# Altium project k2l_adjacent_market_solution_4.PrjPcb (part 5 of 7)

## Sheet dac38j84_03.SchDoc
size 431 x 279 mm; Date: Not shown in title block; ApprovedBy: Not shown in title block; CheckedBy: Not shown in title block; Author: Not shown in title block; CompanyName: Not shown in title block; Engineer: Not shown in title block; Organization: Not shown in title block; Address1: Not shown in title block; Address2: Not shown in title block; Address3: Not shown in title block; Address4: Not shown in title block; DocumentNumber: 29; Revision: Use project parameter SCH_Rev; SheetNumber: 29; SheetTotal: 38; PageSetup: Record=PageOptions¦CenterHorizontal=True¦CenterVertical=True¦PrintScale=1.00¦XCorrection=1.00¦YCorrection=1.00¦PrintKind=0¦BorderSize=5000000¦LeftOffset=0¦BottomOffset=0¦Orientation=2¦PaperLength=1000¦PaperWidth=1000¦Scale=100¦PaperSource=15¦PrintQuality=600¦MediaType=1¦DitherType=10¦PaperKind=Letter¦PrintScaleMode=1
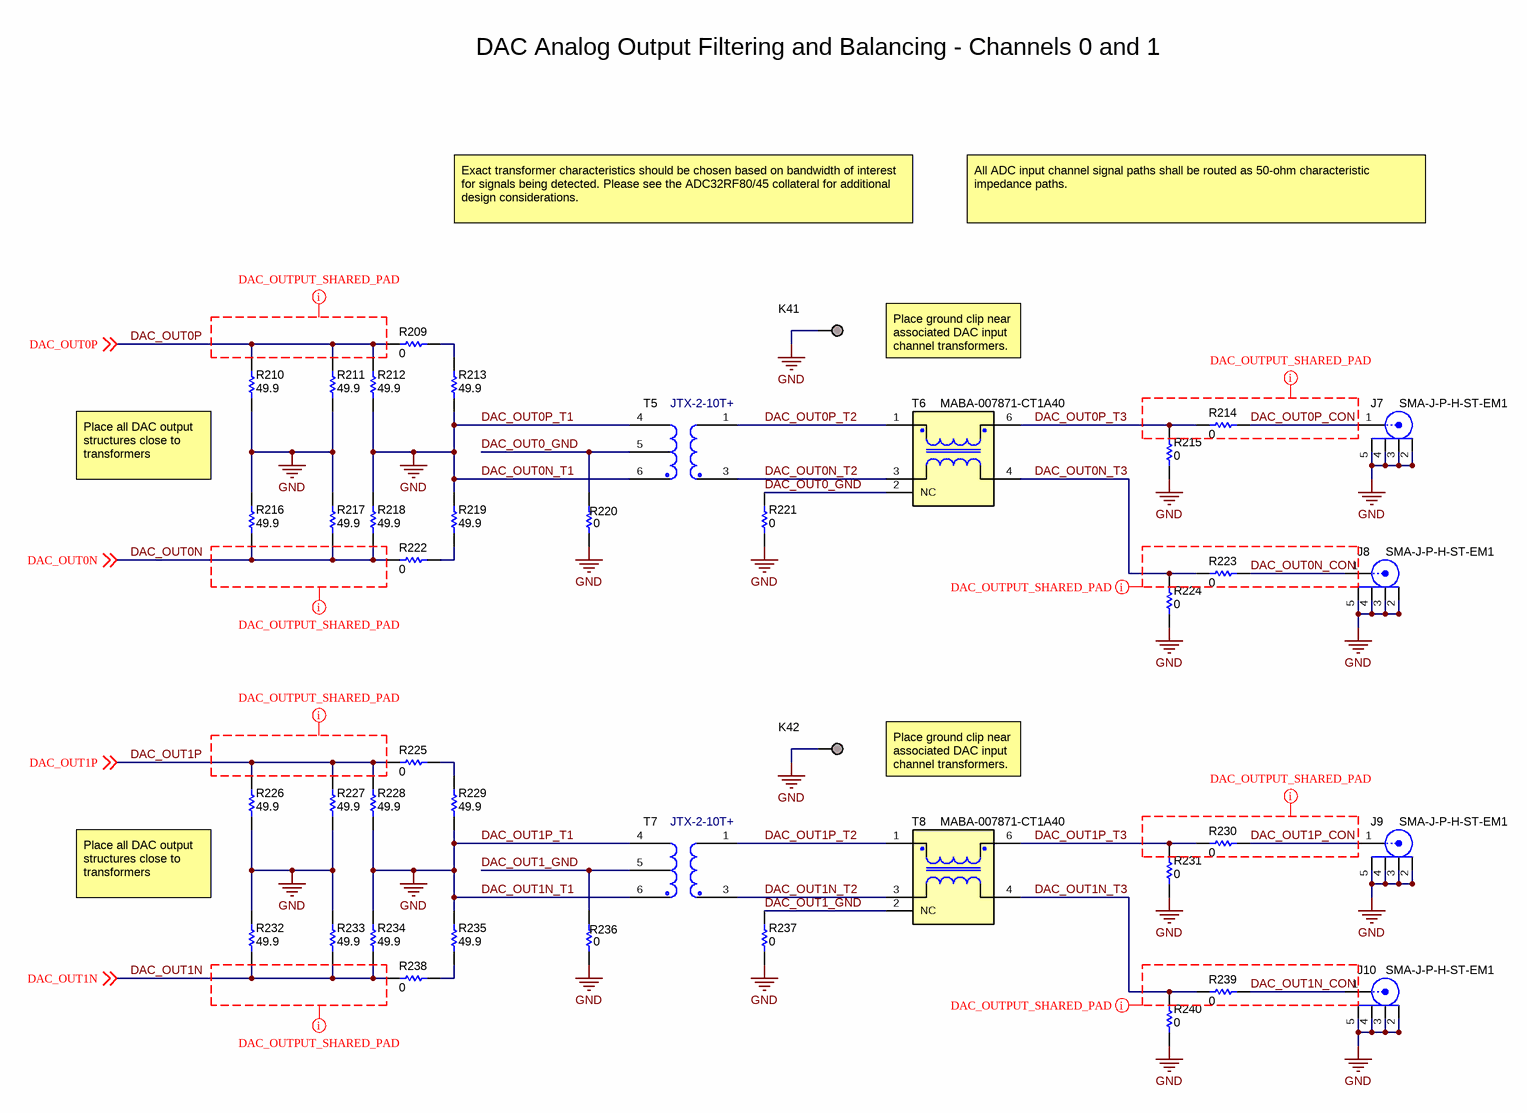
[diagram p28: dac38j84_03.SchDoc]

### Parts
J7  SMA-J-P-H-ST-EM1  [Samtec_SMA-J-P-H-ST-EM1]
J8  SMA-J-P-H-ST-EM1  [Samtec_SMA-J-P-H-ST-EM1]
J9  SMA-J-P-H-ST-EM1  [Samtec_SMA-J-P-H-ST-EM1]
J10  SMA-J-P-H-ST-EM1  [Samtec_SMA-J-P-H-ST-EM1]
K41  TESTPOINT  [TESTPOINT]  (value not drawn)  (no BOM)
K42  TESTPOINT  [TESTPOINT]  (value not drawn)  (no BOM)
R209  ValueDisplayed: 0  [0402]  (hidden comment: CRCW04020000Z0ED)
R210  ValueDisplayed: 49.9  [0402]  (hidden comment: CRCW040249R9FKED)
R211  ValueDisplayed: 49.9  [0402]  (hidden comment: CRCW040249R9FKED)
R212  ValueDisplayed: 49.9  [0402]  (hidden comment: CRCW040249R9FKED)
R213  ValueDisplayed: 49.9  [0402]  (hidden comment: CRCW040249R9FKED)
R214  ValueDisplayed: 0  [0402]  (hidden comment: CRCW04020000Z0ED)
R215  ValueDisplayed: 0  [0402]  (hidden comment: CRCW04020000Z0ED)
R216  ValueDisplayed: 49.9  [0402]  (hidden comment: CRCW040249R9FKED)
R217  ValueDisplayed: 49.9  [0402]  (hidden comment: CRCW040249R9FKED)
R218  ValueDisplayed: 49.9  [0402]  (hidden comment: CRCW040249R9FKED)
R219  ValueDisplayed: 49.9  [0402]  (hidden comment: CRCW040249R9FKED)
R220  ValueDisplayed: 0  [0402]  (hidden comment: CRCW04020000Z0ED)
R221  ValueDisplayed: 0  [0402]  (hidden comment: CRCW04020000Z0ED)
R222  ValueDisplayed: 0  [0402]  (hidden comment: CRCW04020000Z0ED)
R223  ValueDisplayed: 0  [0402]  (hidden comment: CRCW04020000Z0ED)
R224  ValueDisplayed: 0  [0402]  (hidden comment: CRCW04020000Z0ED)
R225  ValueDisplayed: 0  [0402]  (hidden comment: CRCW04020000Z0ED)
R226  ValueDisplayed: 49.9  [0402]  (hidden comment: CRCW040249R9FKED)
R227  ValueDisplayed: 49.9  [0402]  (hidden comment: CRCW040249R9FKED)
R228  ValueDisplayed: 49.9  [0402]  (hidden comment: CRCW040249R9FKED)
R229  ValueDisplayed: 49.9  [0402]  (hidden comment: CRCW040249R9FKED)
R230  ValueDisplayed: 0  [0402]  (hidden comment: CRCW04020000Z0ED)
R231  ValueDisplayed: 0  [0402]  (hidden comment: CRCW04020000Z0ED)
R232  ValueDisplayed: 49.9  [0402]  (hidden comment: CRCW040249R9FKED)
R233  ValueDisplayed: 49.9  [0402]  (hidden comment: CRCW040249R9FKED)
R234  ValueDisplayed: 49.9  [0402]  (hidden comment: CRCW040249R9FKED)
R235  ValueDisplayed: 49.9  [0402]  (hidden comment: CRCW040249R9FKED)
R236  ValueDisplayed: 0  [0402]  (hidden comment: CRCW04020000Z0ED)
R237  ValueDisplayed: 0  [0402]  (hidden comment: CRCW04020000Z0ED)
R238  ValueDisplayed: 0  [0402]  (hidden comment: CRCW04020000Z0ED)
R239  ValueDisplayed: 0  [0402]  (hidden comment: CRCW04020000Z0ED)
R240  ValueDisplayed: 0  [0402]  (hidden comment: CRCW04020000Z0ED)
T5  JTX-2-10T+  [Mini-Circuits_BH292]
T6  MABA-007871-CT1A40  [MACOM_MABA-007871]
T7  JTX-2-10T+  [Mini-Circuits_BH292]
T8  MABA-007871-CT1A40  [MACOM_MABA-007871]

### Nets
DAC_OUT0N_T1: J7.2 J7.3 J7.4 J7.5 J8.2 J8.3 J8.4 J8.5 J9.2 J9.3 J9.4 J9.5 J10.2 J10.3 J10.4 J10.5 K41.1 K42.1 R210.1 R211.1 R212.1 R213.1 R215.1 R216.2 R217.2 R218.2 R219.2 R220.1 R221.1 R224.1 R226.1 R227.1 R228.1 R229.1 R231.1 R232.2 R233.2 R234.2 R235.2 R236.1 R237.1 R240.1 T5.4 T5.6 T7.4 T7.6  [also labelled DAC_OUT0P_T1, DAC_OUT1N_T1, DAC_OUT1P_T1, GND]
DAC_OUT0_GND: R220.2 R221.2 T5.5 T6.2(NC)
DAC_OUT0N: R216.1 R217.1 R218.1 R222.2 ; off-sheet DAC_OUT0N
DAC_OUT0N_CON: J8.1 R223.2
DAC_OUT0N_T2: T5.3 T6.3
DAC_OUT0N_T3: R223.1 R224.2 T6.4(GND)
DAC_OUT0P: R209.2 R210.2 R211.2 R212.2 ; off-sheet DAC_OUT0P
DAC_OUT0P_CON: J7.1 R214.2
DAC_OUT0P_T2: T5.1 T6.1
DAC_OUT0P_T3: R214.1 R215.2 T6.6
DAC_OUT1_GND: R236.2 R237.2 T7.5 T8.2(NC)
DAC_OUT1N: R232.1 R233.1 R234.1 R238.2 ; off-sheet DAC_OUT1N
DAC_OUT1N_CON: J10.1 R239.2
DAC_OUT1N_T2: T7.3 T8.3
DAC_OUT1N_T3: R239.1 R240.2 T8.4(GND)
DAC_OUT1P: R225.2 R226.2 R227.2 R228.2 ; off-sheet DAC_OUT1P
DAC_OUT1P_CON: J9.1 R230.2
DAC_OUT1P_T2: T7.1 T8.1
DAC_OUT1P_T3: R230.1 R231.2 T8.6
NetR209_1: R209.1 R213.2
NetR219_1: R219.1 R222.1
NetR225_1: R225.1 R229.2
NetR235_1: R235.1 R238.1

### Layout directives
net class Undefined: (no net found under the mark), DAC_OUT0N_CON, DAC_OUT0P_CON, DAC_OUT1N_CON, DAC_OUT1P_CON

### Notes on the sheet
- DAC Analog Output Filtering and Balancing - Channels 0 and 1
- Exact transformer characteristics should be chosen based on bandwidth of interest for signals being detected. Please see the ADC32RF80/45 collateral for additional design considerations.
- All ADC input channel signal paths shall be routed as 50-ohm characteristic impedance paths.
- Place ground clip near associated DAC input channel transformers.
- Place all DAC output
  structures close to transformers

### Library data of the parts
J7-J10 = SMA-J-P-H-ST-EM1: SMA Jack, 50 Ohm, Gold, R/A, SMT; Manufacturer: Samtec; SymbolCreator: X0208326; Pitch_mm: 2.825; Gender: Female; Shrouded: Y; Voltage_V: 335
K41 K42 = TESTPOINT: TEST POINT.  No entry in BOM.
R209 R214 R215 R220-R225 R230 R231 R236-R240 = CRCW04020000Z0ED: RES, 0, 5%, 0.063 W, 0402; Manufacturer: Vishay-Dale; CompType: Resistor; Value: 0; Value_Code: 0000; Tolerance_%: 5; Power_W: 0.063; Value2: 0.063W; VDC_V: 50; TempCo: 200 ppm/C; SizeArea_mm2: 0.5; SizeX_mm: 1; SizeZ_mm: 0.6; EIA_Code: E24; U/M: EA; AEC Category: Q200
R210-R213 R216-R219 R226-R229 R232-R235 = CRCW040249R9FKED: RES, 49.9, 1%, 0.063 W, 0402; Manufacturer: Vishay-Dale; CompType: Resistor; Value: 49.9; Value_Code: 49R9; Tolerance_%: 1; Power_W: 0.063; Value2: 0.063W; VDC_V: 50; TempCo: 100 ppm/C; SizeArea_mm2: 0.5; SizeZ_mm: 0.6; EIA_Code: E96; U/M: EA; AEC Category: Q200
T5 T7 = JTX-2-10T+: RF Transformer, SMT; Manufacturer: Minicircuits; SymbolCreator: x0208325
T6 T8 = MABA-007871-CT1A40: Transformer, SMT; Manufacturer: MACOM; SymbolCreator: Altium; Ns1toNp: 1; SizeAreaWB_mm2: 27.1962; SizeArea_mm2: 17.7662; SizeX_mm: 4.21; SizeY_mm: 4.22; SizeZ_mm: 2.926

## Sheet dac38j84_04.SchDoc
size 431 x 279 mm; Date: Not shown in title block; ApprovedBy: Not shown in title block; CheckedBy: Not shown in title block; Author: Not shown in title block; CompanyName: Not shown in title block; Engineer: Not shown in title block; Organization: Not shown in title block; Address1: Not shown in title block; Address2: Not shown in title block; Address3: Not shown in title block; Address4: Not shown in title block; DocumentNumber: 30; Revision: Use project parameter SCH_Rev; SheetNumber: 30; SheetTotal: 38; PageSetup: Record=PageOptions¦CenterHorizontal=True¦CenterVertical=True¦PrintScale=1.00¦XCorrection=1.00¦YCorrection=1.00¦PrintKind=0¦BorderSize=5000000¦LeftOffset=0¦BottomOffset=0¦Orientation=2¦PaperLength=1000¦PaperWidth=1000¦Scale=100¦PaperSource=15¦PrintQuality=600¦MediaType=1¦DitherType=10¦PaperKind=Letter¦PrintScaleMode=1
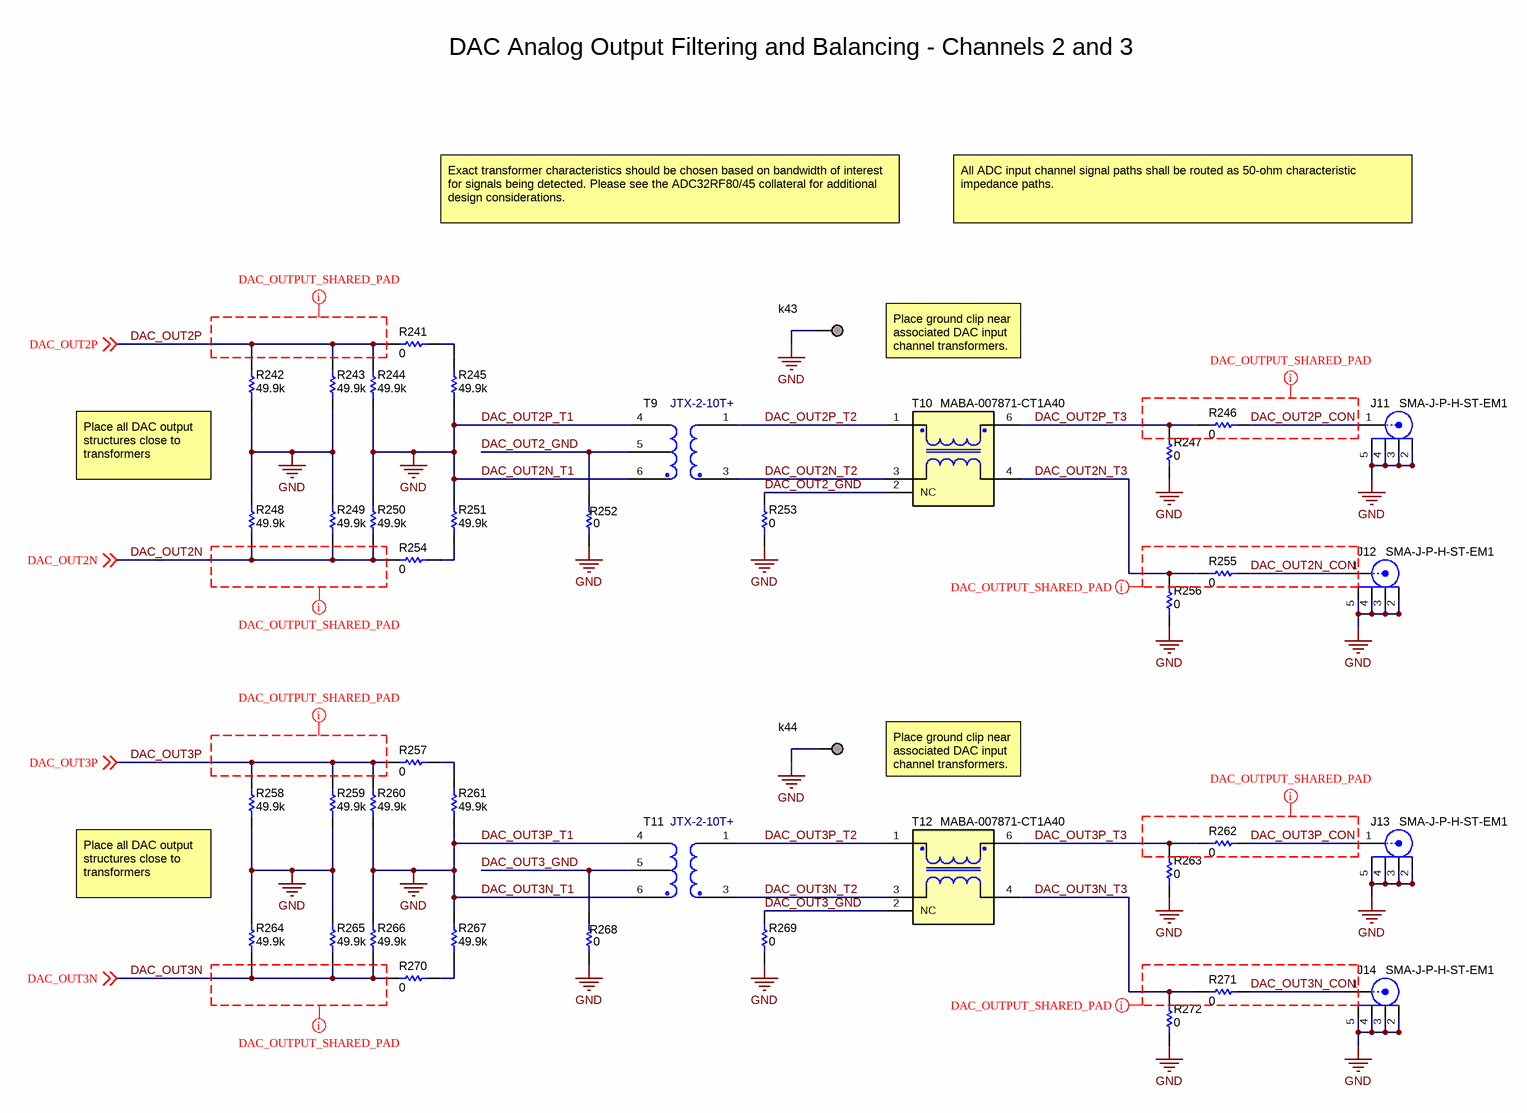
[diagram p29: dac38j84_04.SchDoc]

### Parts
J11  SMA-J-P-H-ST-EM1  [Samtec_SMA-J-P-H-ST-EM1]
J12  SMA-J-P-H-ST-EM1  [Samtec_SMA-J-P-H-ST-EM1]
J13  SMA-J-P-H-ST-EM1  [Samtec_SMA-J-P-H-ST-EM1]
J14  SMA-J-P-H-ST-EM1  [Samtec_SMA-J-P-H-ST-EM1]
k43  TESTPOINT  [TESTPOINT]  (value not drawn)  (no BOM)
k44  TESTPOINT  [TESTPOINT]  (value not drawn)  (no BOM)
R241  ValueDisplayed: 0  [0402]  (hidden comment: CRCW04020000Z0ED)
R242  ValueDisplayed: 49.9k  [0402]  (hidden comment: CRCW040249K9FKED)
R243  ValueDisplayed: 49.9k  [0402]  (hidden comment: CRCW040249K9FKED)
R244  ValueDisplayed: 49.9k  [0402]  (hidden comment: CRCW040249K9FKED)
R245  ValueDisplayed: 49.9k  [0402]  (hidden comment: CRCW040249K9FKED)
R246  ValueDisplayed: 0  [0402]  (hidden comment: CRCW04020000Z0ED)
R247  ValueDisplayed: 0  [0402]  (hidden comment: CRCW04020000Z0ED)
R248  ValueDisplayed: 49.9k  [0402]  (hidden comment: CRCW040249K9FKED)
R249  ValueDisplayed: 49.9k  [0402]  (hidden comment: CRCW040249K9FKED)
R250  ValueDisplayed: 49.9k  [0402]  (hidden comment: CRCW040249K9FKED)
R251  ValueDisplayed: 49.9k  [0402]  (hidden comment: CRCW040249K9FKED)
R252  ValueDisplayed: 0  [0402]  (hidden comment: CRCW04020000Z0ED)
R253  ValueDisplayed: 0  [0402]  (hidden comment: CRCW04020000Z0ED)
R254  ValueDisplayed: 0  [0402]  (hidden comment: CRCW04020000Z0ED)
R255  ValueDisplayed: 0  [0402]  (hidden comment: CRCW04020000Z0ED)
R256  ValueDisplayed: 0  [0402]  (hidden comment: CRCW04020000Z0ED)
R257  ValueDisplayed: 0  [0402]  (hidden comment: CRCW04020000Z0ED)
R258  ValueDisplayed: 49.9k  [0402]  (hidden comment: CRCW040249K9FKED)
R259  ValueDisplayed: 49.9k  [0402]  (hidden comment: CRCW040249K9FKED)
R260  ValueDisplayed: 49.9k  [0402]  (hidden comment: CRCW040249K9FKED)
R261  ValueDisplayed: 49.9k  [0402]  (hidden comment: CRCW040249K9FKED)
R262  ValueDisplayed: 0  [0402]  (hidden comment: CRCW04020000Z0ED)
R263  ValueDisplayed: 0  [0402]  (hidden comment: CRCW04020000Z0ED)
R264  ValueDisplayed: 49.9k  [0402]  (hidden comment: CRCW040249K9FKED)
R265  ValueDisplayed: 49.9k  [0402]  (hidden comment: CRCW040249K9FKED)
R266  ValueDisplayed: 49.9k  [0402]  (hidden comment: CRCW040249K9FKED)
R267  ValueDisplayed: 49.9k  [0402]  (hidden comment: CRCW040249K9FKED)
R268  ValueDisplayed: 0  [0402]  (hidden comment: CRCW04020000Z0ED)
R269  ValueDisplayed: 0  [0402]  (hidden comment: CRCW04020000Z0ED)
R270  ValueDisplayed: 0  [0402]  (hidden comment: CRCW04020000Z0ED)
R271  ValueDisplayed: 0  [0402]  (hidden comment: CRCW04020000Z0ED)
R272  ValueDisplayed: 0  [0402]  (hidden comment: CRCW04020000Z0ED)
T9  JTX-2-10T+  [Mini-Circuits_BH292]
T10  MABA-007871-CT1A40  [MACOM_MABA-007871]
T11  JTX-2-10T+  [Mini-Circuits_BH292]
T12  MABA-007871-CT1A40  [MACOM_MABA-007871]

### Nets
DAC_OUT2N_T1: J11.2 J11.3 J11.4 J11.5 J12.2 J12.3 J12.4 J12.5 J13.2 J13.3 J13.4 J13.5 J14.2 J14.3 J14.4 J14.5 k43.1 k44.1 R242.1 R243.1 R244.1 R245.1 R247.1 R248.2 R249.2 R250.2 R251.2 R252.1 R253.1 R256.1 R258.1 R259.1 R260.1 R261.1 R263.1 R264.2 R265.2 R266.2 R267.2 R268.1 R269.1 R272.1 T9.4 T9.6 T11.4 T11.6  [also labelled DAC_OUT2P_T1, DAC_OUT3N_T1, DAC_OUT3P_T1, GND]  [project net DAC_OUT0N_T1]
DAC_OUT2_GND: R252.2 R253.2 T9.5 T10.2(NC)
DAC_OUT2N: R248.1 R249.1 R250.1 R254.2 ; off-sheet DAC_OUT2N
DAC_OUT2N_CON: J12.1 R255.2
DAC_OUT2N_T2: T9.3 T10.3
DAC_OUT2N_T3: R255.1 R256.2 T10.4(GND)
DAC_OUT2P: R241.2 R242.2 R243.2 R244.2 ; off-sheet DAC_OUT2P
DAC_OUT2P_CON: J11.1 R246.2
DAC_OUT2P_T2: T9.1 T10.1
DAC_OUT2P_T3: R246.1 R247.2 T10.6
DAC_OUT3_GND: R268.2 R269.2 T11.5 T12.2(NC)
DAC_OUT3N: R264.1 R265.1 R266.1 R270.2 ; off-sheet DAC_OUT3N
DAC_OUT3N_CON: J14.1 R271.2
DAC_OUT3N_T2: T11.3 T12.3
DAC_OUT3N_T3: R271.1 R272.2 T12.4(GND)
DAC_OUT3P: R257.2 R258.2 R259.2 R260.2 ; off-sheet DAC_OUT3P
DAC_OUT3P_CON: J13.1 R262.2
DAC_OUT3P_T2: T11.1 T12.1
DAC_OUT3P_T3: R262.1 R263.2 T12.6
NetR241_1: R241.1 R245.2
NetR251_1: R251.1 R254.1
NetR257_1: R257.1 R261.2
NetR267_1: R267.1 R270.1

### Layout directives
net class Undefined: (no net found under the mark), DAC_OUT2N_CON, DAC_OUT2P_CON, DAC_OUT3N_CON, DAC_OUT3P_CON

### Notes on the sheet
- DAC Analog Output Filtering and Balancing - Channels 2 and 3
- Exact transformer characteristics should be chosen based on bandwidth of interest for signals being detected. Please see the ADC32RF80/45 collateral for additional design considerations.
- All ADC input channel signal paths shall be routed as 50-ohm characteristic impedance paths.
- Place ground clip near associated DAC input channel transformers.
- Place all DAC output
  structures close to transformers

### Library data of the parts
J11-J14 = SMA-J-P-H-ST-EM1: as J7-J10 on sheet dac38j84_03
k43 k44 = TESTPOINT: TEST POINT.  No entry in BOM.
R241 R246 R247 R252-R257 R262 R263 R268-R272 = CRCW04020000Z0ED: as R209 on sheet dac38j84_03
R242-R245 R248-R251 R258-R261 R264-R267 = CRCW040249K9FKED: RES, 49.9 k, 1%, 0.063 W, 0402; Manufacturer: Vishay-Dale; CompType: Resistor; Value: 49.9k; Res_ohm: 49900; Value_Code: 49k9; Tolerance_%: 1; Power_W: 0.063; Value2: 0.063W; VDC_V: 50; TempCo: 100 ppm/C; SizeArea_mm2: 0.5; SizeZ_mm: 0.6; EIA_Code: E96; U/M: EA; AEC Category: Q200
T9 T11 = JTX-2-10T+: as T5 on sheet dac38j84_03
T10 T12 = MABA-007871-CT1A40: as T6 on sheet dac38j84_03

## Sheet lmk04828_01.SchDoc
size 431 x 279 mm; Date: Not shown in title block; ApprovedBy: Not shown in title block; CheckedBy: Not shown in title block; Author: Not shown in title block; CompanyName: Not shown in title block; Engineer: Not shown in title block; Organization: Not shown in title block; Address1: Not shown in title block; Address2: Not shown in title block; Address3: Not shown in title block; Address4: Not shown in title block; DocumentNumber: 31; Revision: Use project parameter SCH_Rev; SheetNumber: 31; SheetTotal: 38; PageSetup: Record=PageOptions¦CenterHorizontal=True¦CenterVertical=True¦PrintScale=1.00¦XCorrection=1.00¦YCorrection=1.00¦PrintKind=0¦BorderSize=5000000¦LeftOffset=0¦BottomOffset=0¦Orientation=2¦PaperLength=1000¦PaperWidth=1000¦Scale=100¦PaperSource=15¦PrintQuality=600¦MediaType=1¦DitherType=10¦PaperKind=Letter¦PrintScaleMode=1
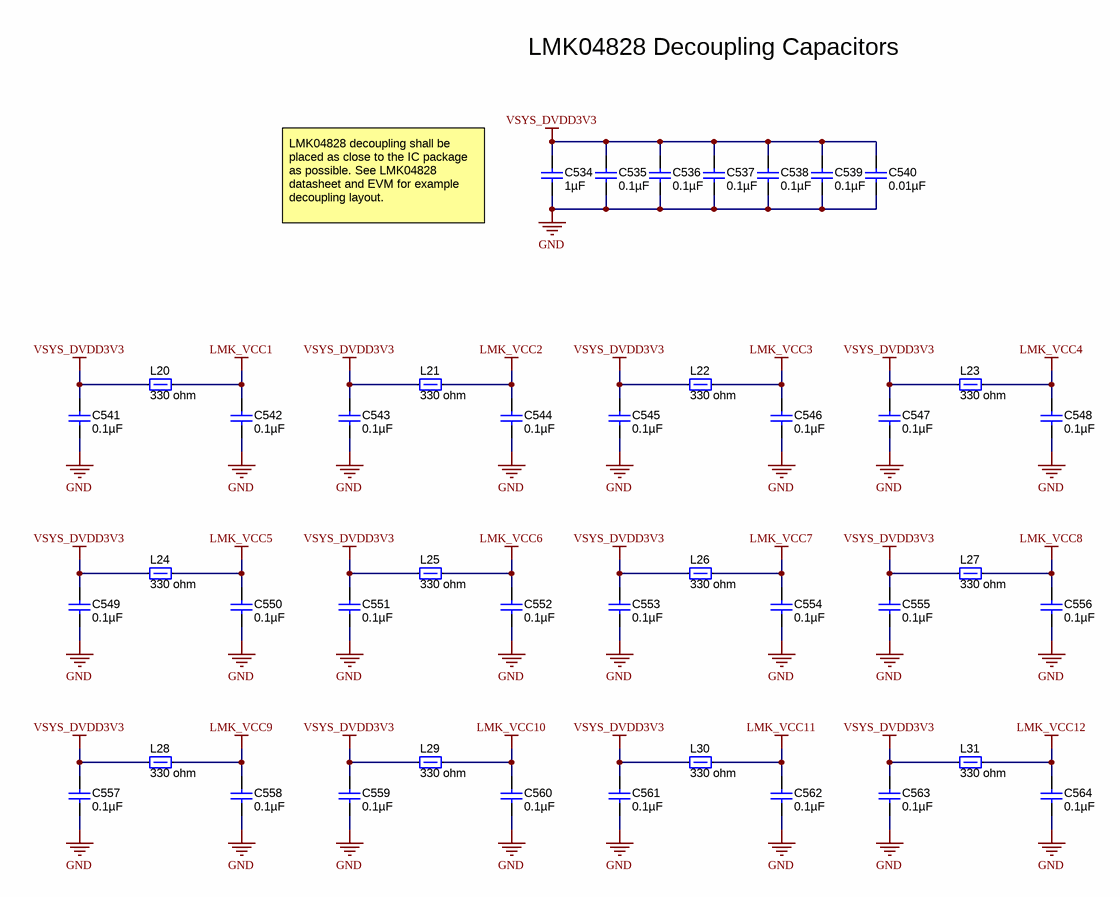
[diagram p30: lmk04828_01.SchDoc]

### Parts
C534  ValueDisplayed: 1µF  [0603L]  (hidden comment: C1608X5R1C105K)
C535  ValueDisplayed: 0.1µF  [0402L]  (hidden comment: C1005X5R1A104K)
C536  ValueDisplayed: 0.1µF  [0402L]  (hidden comment: C1005X5R1A104K)
C537  ValueDisplayed: 0.1µF  [0402L]  (hidden comment: C1005X5R1A104K)
C538  ValueDisplayed: 0.1µF  [0402L]  (hidden comment: C1005X5R1A104K)
C539  ValueDisplayed: 0.1µF  [0402L]  (hidden comment: C1005X5R1A104K)
C540  ValueDisplayed: 0.01µF  [0402L]  (hidden comment: C1005X7R1C103K)
C541  ValueDisplayed: 0.1µF  [0402L]  (hidden comment: C1005X5R1A104K)
C542  ValueDisplayed: 0.1µF  [0402L]  (hidden comment: C1005X5R1A104K)
C543  ValueDisplayed: 0.1µF  [0402L]  (hidden comment: C1005X5R1A104K)
C544  ValueDisplayed: 0.1µF  [0402L]  (hidden comment: C1005X5R1A104K)
C545  ValueDisplayed: 0.1µF  [0402L]  (hidden comment: C1005X5R1A104K)
C546  ValueDisplayed: 0.1µF  [0402L]  (hidden comment: C1005X5R1A104K)
C547  ValueDisplayed: 0.1µF  [0402L]  (hidden comment: C1005X5R1A104K)
C548  ValueDisplayed: 0.1µF  [0402L]  (hidden comment: C1005X5R1A104K)
C549  ValueDisplayed: 0.1µF  [0402L]  (hidden comment: C1005X5R1A104K)
C550  ValueDisplayed: 0.1µF  [0402L]  (hidden comment: C1005X5R1A104K)
C551  ValueDisplayed: 0.1µF  [0402L]  (hidden comment: C1005X5R1A104K)
C552  ValueDisplayed: 0.1µF  [0402L]  (hidden comment: C1005X5R1A104K)
C553  ValueDisplayed: 0.1µF  [0402L]  (hidden comment: C1005X5R1A104K)
C554  ValueDisplayed: 0.1µF  [0402L]  (hidden comment: C1005X5R1A104K)
C555  ValueDisplayed: 0.1µF  [0402L]  (hidden comment: C1005X5R1A104K)
C556  ValueDisplayed: 0.1µF  [0402L]  (hidden comment: C1005X5R1A104K)
C557  ValueDisplayed: 0.1µF  [0402L]  (hidden comment: C1005X5R1A104K)
C558  ValueDisplayed: 0.1µF  [0402L]  (hidden comment: C1005X5R1A104K)
C559  ValueDisplayed: 0.1µF  [0402L]  (hidden comment: C1005X5R1A104K)
C560  ValueDisplayed: 0.1µF  [0402L]  (hidden comment: C1005X5R1A104K)
C561  ValueDisplayed: 0.1µF  [0402L]  (hidden comment: C1005X5R1A104K)
C562  ValueDisplayed: 0.1µF  [0402L]  (hidden comment: C1005X5R1A104K)
C563  ValueDisplayed: 0.1µF  [0402L]  (hidden comment: C1005X5R1A104K)
C564  ValueDisplayed: 0.1µF  [0402L]  (hidden comment: C1005X5R1A104K)
L20  value 330 ohm  [0603]  (hidden comment: BLM18SG331TN1D)
L21  value 330 ohm  [0603]  (hidden comment: BLM18SG331TN1D)
L22  value 330 ohm  [0603]  (hidden comment: BLM18SG331TN1D)
L23  value 330 ohm  [0603]  (hidden comment: BLM18SG331TN1D)
L24  value 330 ohm  [0603]  (hidden comment: BLM18SG331TN1D)
L25  value 330 ohm  [0603]  (hidden comment: BLM18SG331TN1D)
L26  value 330 ohm  [0603]  (hidden comment: BLM18SG331TN1D)
L27  value 330 ohm  [0603]  (hidden comment: BLM18SG331TN1D)
L28  value 330 ohm  [0603]  (hidden comment: BLM18SG331TN1D)
L29  value 330 ohm  [0603]  (hidden comment: BLM18SG331TN1D)
L30  value 330 ohm  [0603]  (hidden comment: BLM18SG331TN1D)
L31  value 330 ohm  [0603]  (hidden comment: BLM18SG331TN1D)

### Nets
GND: C534.2 C535.2 C536.2 C537.2 C538.2 C539.2 C540.2 C541.2 C542.2 C543.2 C544.2 C545.2 C546.2 C547.2 C548.2 C549.2 C550.2 C551.2 C552.2 C553.2 C554.2 C555.2 C556.2 C557.2 C558.2 C559.2 C560.2 C561.2 C562.2 C563.2 C564.2  [project net DAC_OUT0N_T1]
LMK_VCC1: C542.1 L20.2
LMK_VCC2: C544.1 L21.2
LMK_VCC3: C546.1 L22.2
LMK_VCC4: C548.1 L23.2
LMK_VCC5: C550.1 L24.2
LMK_VCC6: C552.1 L25.2
LMK_VCC7: C554.1 L26.2
LMK_VCC8: C556.1 L27.2
LMK_VCC9: C558.1 L28.2
LMK_VCC10: C560.1 L29.2
LMK_VCC11: C562.1 L30.2
LMK_VCC12: C564.1 L31.2
VSYS_DVDD3V3: C534.1 C535.1 C536.1 C537.1 C538.1 C539.1 C540.1 C541.1 C543.1 C545.1 C547.1 C549.1 C551.1 C553.1 C555.1 C557.1 C559.1 C561.1 C563.1 L20.1 L21.1 L22.1 L23.1 L24.1 L25.1 L26.1 L27.1 L28.1 L29.1 L30.1 L31.1

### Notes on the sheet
- LMK04828 Decoupling Capacitors
- LMK04828 decoupling shall be placed as close to the IC package as possible. See LMK04828 datasheet and EVM for example decoupling layout.

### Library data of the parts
C534 = C1608X5R1C105K: CAP, CERM, 1uF, 16V, +/-10%, X5R, 0603; Manufacturer: TDK; Polarized: N; CompType: Capacitor; U/M: EA; Cap_F: 0.000001; Tolerance_%: 10; ESR_Ohm: 0.0057; Value1: 0.0057 ohm; VDC_V: 16; TaMin_C: -55; TaMax_C: 85; Cap_Case: 0603
C535-C539 C541-C564 = C1005X5R1A104K: CAP, CERM, 0.1uF, 10V, +/-10%, X5R, 0402; Manufacturer: TDK; Polarized: N; CompType: Capacitor; U/M: EA; Cap_F: 0.0000001; Tolerance_%: 10; ESR_Ohm: 0.0186; Value1: 0.0186 ohm; TaMin_C: -55; TaMax_C: 85; Cap_Case: 0402
C540 = C1005X7R1C103K: CAP, CERM, 0.01uF, 16V, +/-10%, X7R, 0402; Manufacturer: TDK; Polarized: N; CompType: Capacitor; U/M: EA; Cap_F: 0.00000001; Tolerance_%: 10; ESR_Ohm: 0.0623; Value1: 0.0623 ohm; VDC_V: 16; TaMin_C: -55; TaMax_C: 125; Cap_Case: 0402
L20-L31 = BLM18SG331TN1D: 1.5A Ferrite Bead, 330 ohm @ 100MHz, SMD; Manufacturer: MuRata; Imax_A: 1.5; DCR_ohm: 0.07; Value1: 0.07 ohm; ZTyp@100MHz_Ohm: 330; U/M: EA

## Sheet lmk04828_02.SchDoc
size 431 x 279 mm; Date: Not shown in title block; ApprovedBy: Not shown in title block; CheckedBy: Not shown in title block; Author: Not shown in title block; CompanyName: Not shown in title block; Engineer: Not shown in title block; Organization: Not shown in title block; Address1: Not shown in title block; Address2: Not shown in title block; Address3: Not shown in title block; Address4: Not shown in title block; DocumentNumber: 32; Revision: Use project parameter SCH_Rev; SheetNumber: 32; SheetTotal: 38; PageSetup: Record=PageOptions¦CenterHorizontal=True¦CenterVertical=True¦PrintScale=1.00¦XCorrection=1.00¦YCorrection=1.00¦PrintKind=0¦BorderSize=5000000¦LeftOffset=0¦BottomOffset=0¦Orientation=2¦PaperLength=1000¦PaperWidth=1000¦Scale=100¦PaperSource=15¦PrintQuality=600¦MediaType=1¦DitherType=10¦PaperKind=Letter¦PrintScaleMode=1
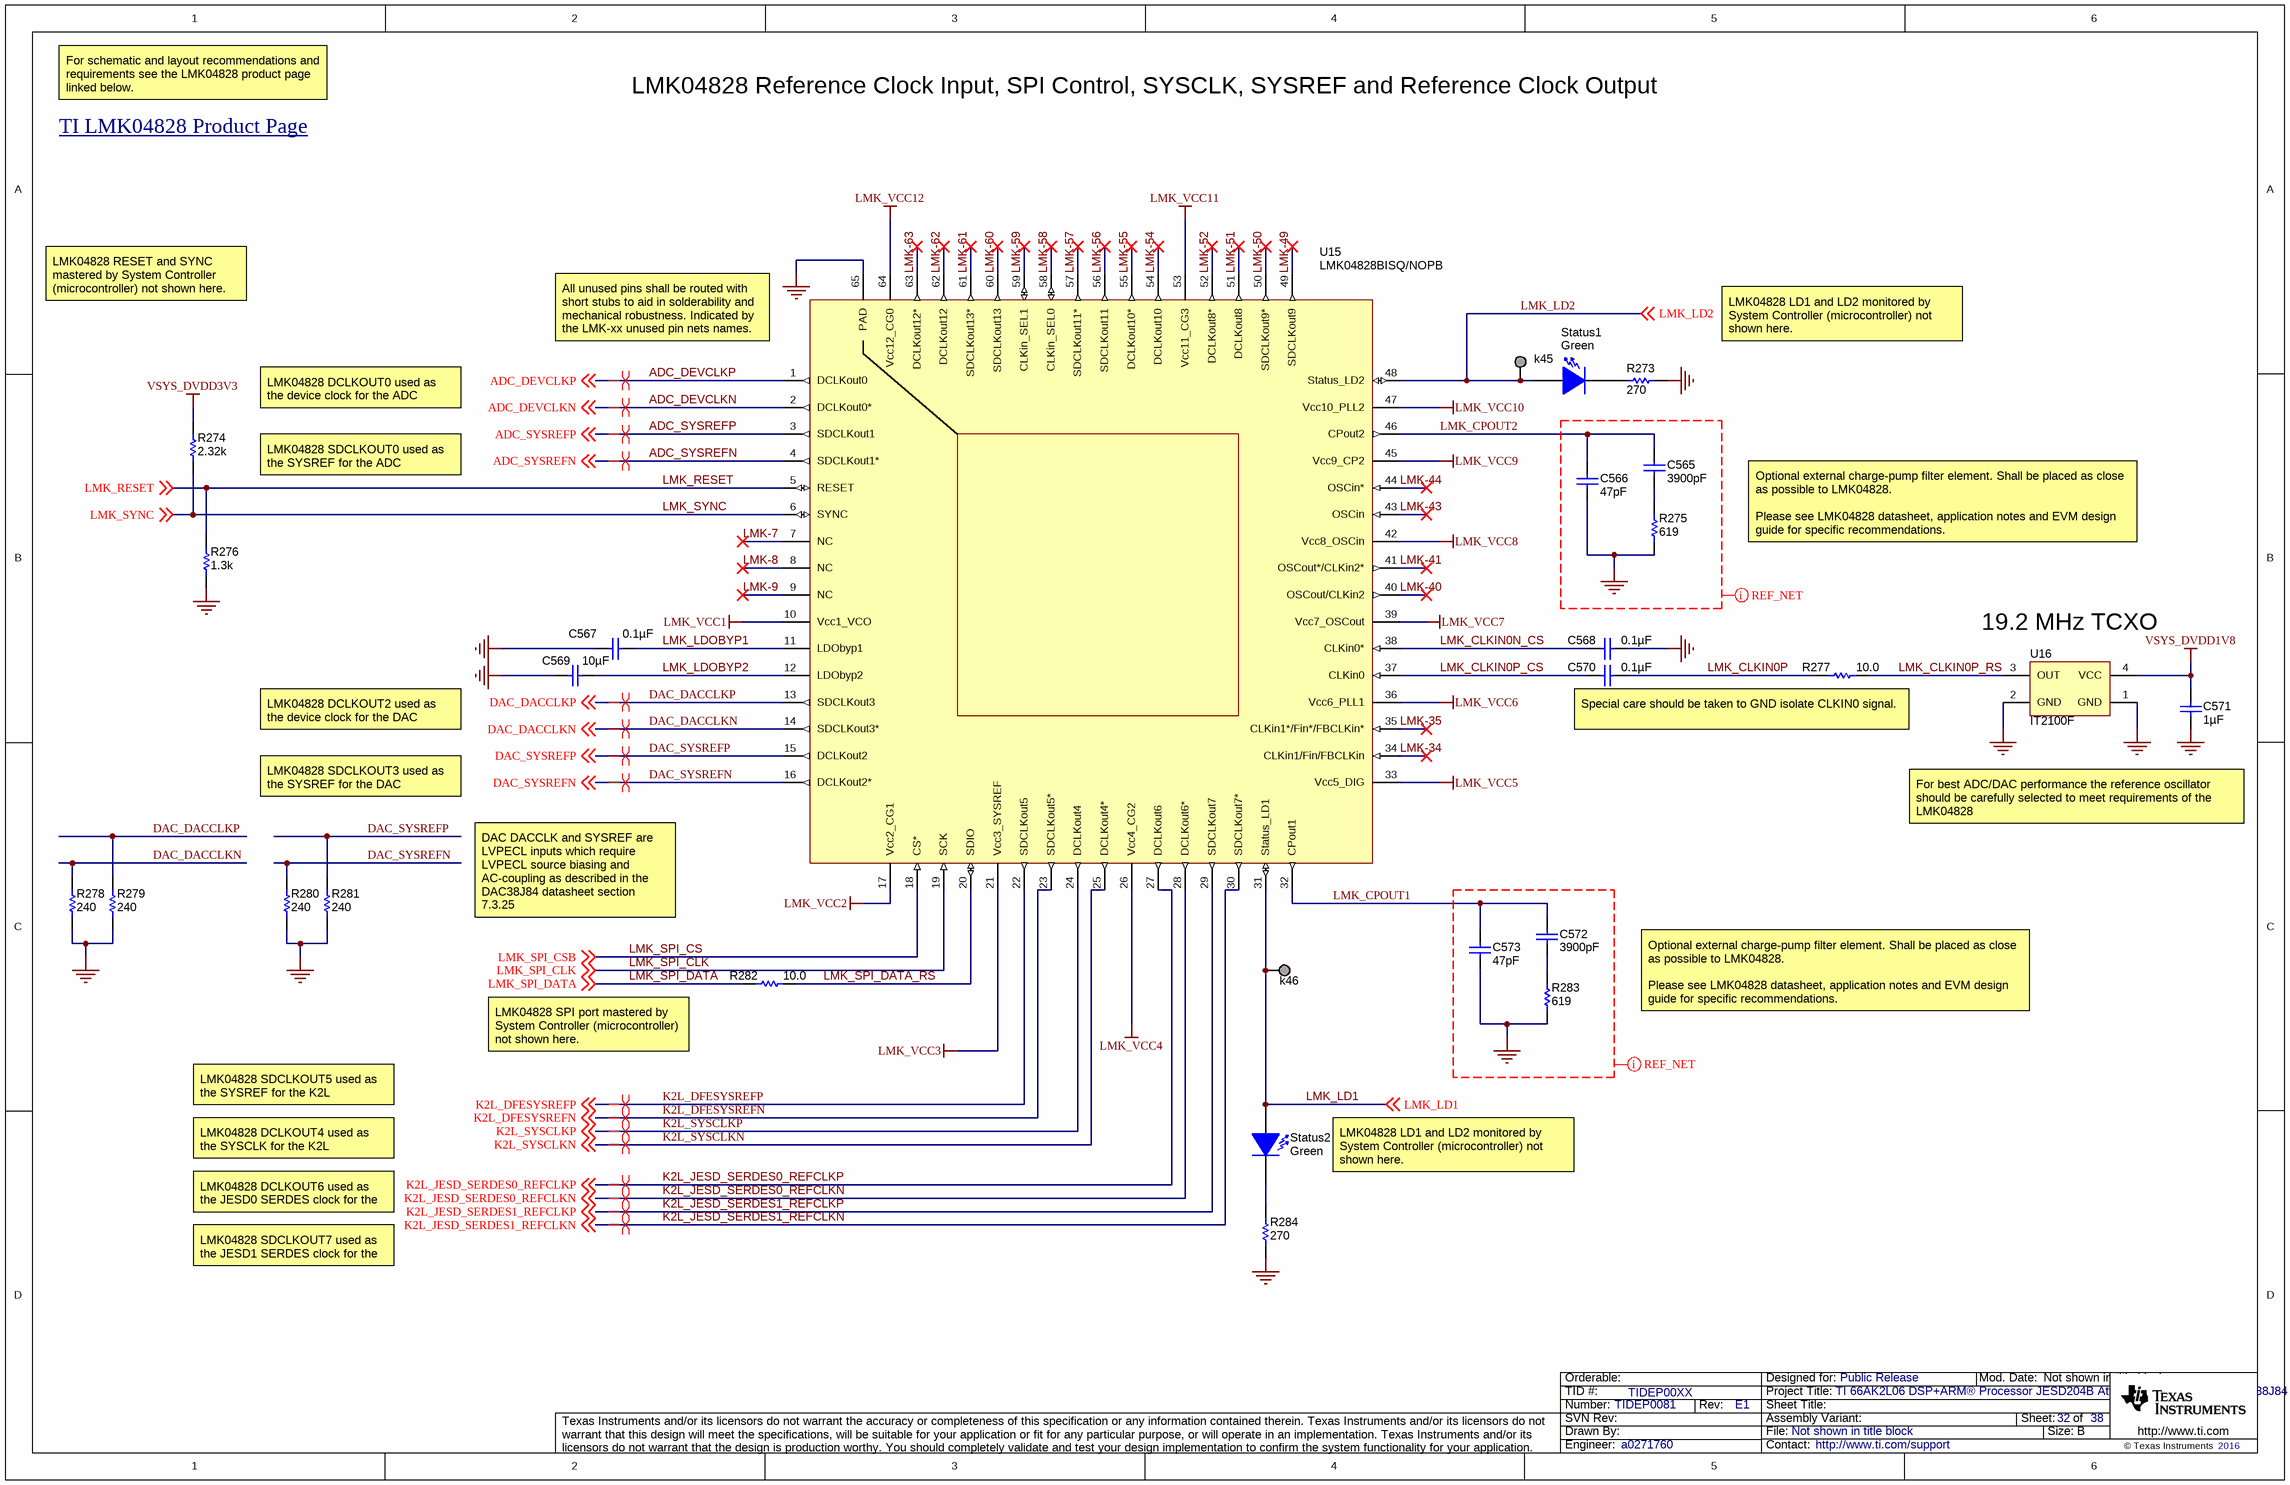
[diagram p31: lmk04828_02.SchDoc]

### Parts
C565  ValueDisplayed: 3900pF  [0603L]  (hidden comment: C1608C0G1E392J)
C566  ValueDisplayed: 47pF  [0603L]  (hidden comment: 06035A470JAT2A)
C567  ValueDisplayed: 0.1µF  [0402L]  (hidden comment: C1005X5R1A104K)
C568  ValueDisplayed: 0.1µF  [0402L]  (hidden comment: C1005X5R1A104K)
C569  ValueDisplayed: 10µF  [0805L]  (hidden comment: C0805C106K8PACTU)
C570  ValueDisplayed: 0.1µF  [0402L]  (hidden comment: C1005X5R1A104K)
C571  ValueDisplayed: 1µF  [0603L]  (hidden comment: C1608X5R1C105K)
C572  ValueDisplayed: 3900pF  [0603L]  (hidden comment: C1608C0G1E392J)
C573  ValueDisplayed: 47pF  [0603L]  (hidden comment: 06035A470JAT2A)
k45  TESTPOINT  [TESTPOINT]  (value not drawn)  (no BOM)
k46  TESTPOINT  [TESTPOINT]  (value not drawn)  (no BOM)
R273  value 270  [0603L]  (hidden comment: CRCW0603270RJNEA)
R274  value 2.32k  [0603L]  (hidden comment: RC0603FR-072K32L)
R275  value 619  [0603L]  (hidden comment: RC0603FR-07619RL)
R276  value 1.3k  [0603L]  (hidden comment: RC0603JR-071K3L)
R277  ValueDisplayed: 10.0  [0402]  (hidden comment: CRCW040210R0FKED)
R278  ValueDisplayed: 240  [0402]  (hidden comment: CRCW0402240RJNED)
R279  ValueDisplayed: 240  [0402]  (hidden comment: CRCW0402240RJNED)
R280  ValueDisplayed: 240  [0402]  (hidden comment: CRCW0402240RJNED)
R281  ValueDisplayed: 240  [0402]  (hidden comment: CRCW0402240RJNED)
R282  ValueDisplayed: 10.0  [0402]  (hidden comment: CRCW040210R0FKED)
R283  value 619  [0603L]  (hidden comment: RC0603FR-07619RL)
R284  value 270  [0603L]  (hidden comment: CRCW0603270RJNEA)
Status1  value Green  [LED_LTST-C190]  (hidden comment: LTST-C190GKT)
Status2  value Green  [LED_LTST-C190]  (hidden comment: LTST-C190GKT)
U15  LMK04828BISQ/NOPB  [NKD0064A]
U16  IT2100F

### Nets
GND: C566.2 C567.1 C568.2 C569.1 C571.2 C573.2 R273.1 R275.1 R276.1 R278.1 R279.1 R280.1 R281.1 R283.1 R284.1 U15.65(PAD) U16.1(GND) U16.2(GND)  [project net DAC_OUT0N_T1]
LMK_VCC1: U15.10(Vcc1_VCO)
LMK_VCC2: U15.17(Vcc2_CG1)
LMK_VCC3: U15.21(Vcc3_SYSREF)
LMK_VCC4: U15.26(Vcc4_CG2)
LMK_VCC5: U15.33(Vcc5_DIG)
LMK_VCC6: U15.36(Vcc6_PLL1)
LMK_VCC7: U15.39(Vcc7_OSCout)
LMK_VCC8: U15.42(Vcc8_OSCin)
LMK_VCC9: U15.45(Vcc9_CP2)
LMK_VCC10: U15.47(Vcc10_PLL2)
LMK_VCC11: U15.53(Vcc11_CG3)
LMK_VCC12: U15.64(Vcc12_CG0)
VSYS_DVDD1V8: C571.1 U16.4(VCC)
VSYS_DVDD3V3: R274.2
ADC_DEVCLKN: U15.2(DCLKout0*) ; off-sheet ADC_DEVCLKN
ADC_DEVCLKP: U15.1(DCLKout0) ; off-sheet ADC_DEVCLKP
ADC_SYSREFN: U15.4(SDCLKout1*) ; off-sheet ADC_SYSREFN
ADC_SYSREFP: U15.3(SDCLKout1) ; off-sheet ADC_SYSREFP
DAC_DACCLKN: R278.2 U15.14(SDCLKout3*) ; off-sheet DAC_DACCLKN
DAC_DACCLKP: R279.2 U15.13(SDCLKout3) ; off-sheet DAC_DACCLKP
DAC_SYSREFN: R280.2 U15.16(DCLKout2*) ; off-sheet DAC_SYSREFN
DAC_SYSREFP: R281.2 U15.15(DCLKout2) ; off-sheet DAC_SYSREFP
K2L_DFESYSREFN: U15.23(SDCLKout5*) ; off-sheet K2L_DFESYSREFN
K2L_DFESYSREFP: U15.22(SDCLKout5) ; off-sheet K2L_DFESYSREFP
K2L_JESD_SERDES0_REFCLKN: U15.28(DCLKout6*) ; off-sheet K2L_JESD_SERDES0_REFCLKN
K2L_JESD_SERDES0_REFCLKP: U15.27(DCLKout6) ; off-sheet K2L_JESD_SERDES0_REFCLKP
K2L_JESD_SERDES1_REFCLKN: U15.30(SDCLKout7*) ; off-sheet K2L_JESD_SERDES1_REFCLKN
K2L_JESD_SERDES1_REFCLKP: U15.29(SDCLKout7) ; off-sheet K2L_JESD_SERDES1_REFCLKP
K2L_SYSCLKN: U15.25(DCLKout4*) ; off-sheet K2L_SYSCLKN
K2L_SYSCLKP: U15.24(DCLKout4) ; off-sheet K2L_SYSCLKP
LMK-7: U15.7(NC)
LMK-8: U15.8(NC)
LMK-9: U15.9(NC)
LMK-34: U15.34(CLKin1/Fin/FBCLKin)
LMK-35: U15.35(CLKin1*/Fin*/FBCLKin*)
LMK-40: U15.40(OSCout/CLKin2)
LMK-41: U15.41(OSCout*/CLKin2*)
LMK-43: U15.43(OSCin)
LMK-44: U15.44(OSCin*)
LMK-49: U15.49(SDCLKout9)
LMK-50: U15.50(SDCLKout9*)
LMK-51: U15.51(DCLKout8)
LMK-52: U15.52(DCLKout8*)
LMK-54: U15.54(DCLKout10)
LMK-55: U15.55(DCLKout10*)
LMK-56: U15.56(SDCLKout11)
LMK-57: U15.57(SDCLKout11*)
LMK-58: U15.58(CLKin_SEL0)
LMK-59: U15.59(CLKin_SEL1)
LMK-60: U15.60(SDCLKout13)
LMK-61: U15.61(SDCLKout13*)
LMK-62: U15.62(DCLKout12)
LMK-63: U15.63(DCLKout12*)
LMK_CLKIN0N_CS: C568.1 U15.38(CLKin0*)
LMK_CLKIN0P: C570.2 R277.1
LMK_CLKIN0P_CS: C570.1 U15.37(CLKin0)
LMK_CLKIN0P_RS: R277.2 U16.3(OUT)
LMK_CPOUT1: C572.1 C573.1 U15.32(CPout1)
LMK_CPOUT2: C565.1 C566.1 U15.46(CPout2)
LMK_LD1: k46.1 Status2.1(A) U15.31(Status_LD1) ; off-sheet LMK_LD1
LMK_LD2: k45.1 Status1.1(A) U15.48(Status_LD2) ; off-sheet LMK_LD2
LMK_LDOBYP1: C567.2 U15.11(LDObyp1)
LMK_LDOBYP2: C569.2 U15.12(LDObyp2)
LMK_RESET: R276.2 U15.5(RESET) ; off-sheet LMK_RESET
LMK_SPI_CLK: U15.19(SCK) ; off-sheet LMK_SPI_CLK
LMK_SPI_CS: U15.18(CS*) ; off-sheet LMK_SPI_CSB  [also labelled LMK_SPI_CSB]
LMK_SPI_DATA: R282.1 ; off-sheet LMK_SPI_DATA
LMK_SPI_DATA_RS: R282.2 U15.20(SDIO)
LMK_SYNC: R274.1 U15.6(SYNC) ; off-sheet LMK_SYNC
NetC565_2: C565.2 R275.2
NetC572_2: C572.2 R283.2
NetR273_2: R273.2 Status1.2(K)
NetR284_2: R284.2 Status2.2(K)

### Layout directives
differential pair: ADC_DEVCLKN, ADC_DEVCLKP, ADC_SYSREFN, ADC_SYSREFP, DAC_DACCLKN, DAC_DACCLKP, DAC_SYSREFN, DAC_SYSREFP, K2L_DFESYSREFN, K2L_DFESYSREFP, K2L_JESD_SERDES0_REFCLKN, K2L_JESD_SERDES0_REFCLKP, K2L_JESD_SERDES1_REFCLKN, K2L_JESD_SERDES1_REFCLKP, K2L_SYSCLKN, K2L_SYSCLKP
net class Undefined: GND

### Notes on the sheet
- For schematic and layout recommendations and requirements see the LMK04828 product page linked below.
- LMK04828 Reference Clock Input, SPI Control, SYSCLK, SYSREF and Reference Clock Output
- TI LMK04828 Product Page <http://www.ti.com/product/LMK04828/description>
- LMK04828 RESET and SYNC mastered by System Controller (microcontroller) not shown here.
- (near U15) All unused pins shall be routed with short stubs to aid in solderability and mechanical robustness. Indicated by the LMK-xx unused pin nets names.
- LMK04828 LD1 and LD2 monitored by System Controller (microcontroller) not shown here.
- LMK04828 DCLKOUT0 used as the device clock for the ADC
- LMK04828 SDCLKOUT0 used as the SYSREF for the ADC
- Optional external charge-pump filter element. Shall be placed as close as possible to LMK04828.
  Please see LMK04828 datasheet, application notes and EVM design guide for specific recommendations.
- (near U16) 19.2 MHz TCXO
- LMK04828 DCLKOUT2 used as the device clock for the DAC
- Special care should be taken to GND isolate CLKIN0 signal.
- LMK04828 SDCLKOUT3 used as the SYSREF for the DAC
- For best ADC/DAC performance the reference oscillator should be carefully selected to meet requirements of the LMK04828
- DAC DACCLK and SYSREF are LVPECL inputs which require LVPECL source biasing and AC-coupling as described in the DAC38J84 datasheet section 7.3.25
- LMK04828 SDCLKOUT5 used as the SYSREF for the K2L
- LMK04828 SPI port mastered by System Controller (microcontroller) not shown here.
- LMK04828 DCLKOUT4 used as the SYSCLK for the K2L
- LMK04828 DCLKOUT6 used as the JESD0 SERDES clock for the K2L
- LMK04828 SDCLKOUT7 used as the JESD1 SERDES clock for the K2L

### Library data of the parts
C565 C572 = C1608C0G1E392J: CAP, CERM, 3900pF, 25V, +/-5%, C0G/NP0, 0603; Manufacturer: TDK; Polarized: N; CompType: Capacitor; U/M: EA; Cap_F: 0.0000000039; Tolerance_%: 5; VDC_V: 25; TaMin_C: -55; TaMax_C: 125; Cap_Case: 0603
C566 C573 = 06035A470JAT2A: CAP, CERM, 47pF, 50V, +/-5%, C0G/NP0, 0603; Manufacturer: AVX; Polarized: N; CompType: Capacitor; U/M: EA; Cap_F: 0.000000000047; Tolerance_%: 5; ESR_Ohm: 0.174; Value1: 0.174 ohm; VDC_V: 50; TaMin_C: -55; TaMax_C: 125; Cap_Case: 0603
C567 C568 C570 = C1005X5R1A104K: as C535 on sheet lmk04828_01
C569 = C0805C106K8PACTU: CAP, CERM, 10uF, 10V, +/-10%, X5R, 0805; Manufacturer: Kemet; Cap_Case: 0805; ESR_Ohm: 0.003; IRMS_A: 11.43; Polarized: N; TaMax_C: 85; TaMin_C: -55; Tolerance_%: 10; Cap_F: 10.0E-6; CompType: Capacitor; Value1: 0.003 ohm
C571 = C1608X5R1C105K: as C534 on sheet lmk04828_01
k45 k46 = TESTPOINT: TEST POINT.  No entry in BOM.
R273 R284 = CRCW0603270RJNEA: RES, 270 ohm, 5%, 0.1W, 0603; Manufacturer: Vishay-Dale; Alternate Manufacturer: Any; Alternate PartNumber: Equivalent; CompType: Resistor; Value_Code: 270R; Tolerance_%: 5; Power_W: 0.1; VDC_V: 75; TempCo: 200 ppm/C; EIA_Code: E24; U/M: EA
R274 = RC0603FR-072K32L: RES, 2.32k ohm, 1%, 0.1W, 0603; Manufacturer: Yageo America; CompType: Resistor; Res_ohm: 2320; Value_Code: 2k32; Tolerance_%: 1; Power_W: 0.1; VDC_V: 150; TempCo: 200 ppm/C; EIA_Code: E96; U/M: EA
R275 R283 = RC0603FR-07619RL: RES, 619 ohm, 1%, 0.1W, 0603; Manufacturer: Yageo America; Alternate Manufacturer: Any; Alternate PartNumber: Equivalent; CompType: Resistor; Value_Code: 619R; Tolerance_%: 1; Power_W: 0.1; VDC_V: 150; TempCo: 200 ppm/C; EIA_Code: E96; U/M: EA
R276 = RC0603JR-071K3L: RES, 1.3k ohm, 5%, 0.1W, 0603; Manufacturer: Yageo America; CompType: Resistor; Res_ohm: 1300; Value_Code: 1k30; Tolerance_%: 5; Power_W: 0.1; VDC_V: 50; TempCo: 100 ppm/C; EIA_Code: E24; U/M: EA
R277 R282 = CRCW040210R0FKED: RES, 10.0, 1%, 0.063 W, 0402; Manufacturer: Vishay-Dale; CompType: Resistor; Value: 10.0; Res_ohm: 10; Value_Code: 10R0; Tolerance_%: 1; Power_W: 0.063; Value2: 0.063W; VDC_V: 50; TempCo: 100 ppm/C; EIA_Code: E96; U/M: EA
R278-R281 = CRCW0402240RJNED: RES, 240, 5%, 0.063 W, 0402; Manufacturer: Vishay-Dale; CompType: Resistor; Value: 240; Value_Code: 240R; Tolerance_%: 5; Power_W: 0.063; Value2: 0.063W; VDC_V: 50; TempCo: 200 ppm/C; EIA_Code: E24; U/M: EA
Status1 Status2 = LTST-C190GKT: LED, Green, SMD; Manufacturer: Lite-On; Vf_V: 2.1; Value2: 2.1V; Io_A: 0.02; Power_TotalModule: 0.1; Value1: 0.1W; U/M: EA
U15 = LMK04828BISQ/NOPB: Low-Noise Clock Jitter Cleaner with Dual Loop PLLs, NKD0064A; Alternate Manufacturer: None; Manufacturer: Texas Instruments; SymbolCreator: a0411947/a0412235; CompType: IC; U/M: EA
U16 = IT2100F: High Stability Standard TCXO; Manufacturer: Rakon; SymbolCreator: a0271760; CompType: High Stabilitiy Standard TCXO; U/M: EA, IN, or GM

## Sheet cdcm6208_1.SchDoc
size 431 x 279 mm; Date: Not shown in title block; ApprovedBy: Not shown in title block; CheckedBy: Not shown in title block; Author: Not shown in title block; CompanyName: Not shown in title block; Engineer: Not shown in title block; Organization: Not shown in title block; Address1: Not shown in title block; Address2: Not shown in title block; Address3: Not shown in title block; Address4: Not shown in title block; DocumentNumber: 33; Revision: Use project parameter SCH_Rev; SheetNumber: 33; SheetTotal: 38; PageSetup: Record=PageOptions¦CenterHorizontal=True¦CenterVertical=True¦PrintScale=1.00¦XCorrection=1.00¦YCorrection=1.00¦PrintKind=0¦BorderSize=5000000¦LeftOffset=0¦BottomOffset=0¦Orientation=2¦PaperLength=1000¦PaperWidth=1000¦Scale=100¦PaperSource=15¦PrintQuality=600¦MediaType=1¦DitherType=10¦PaperKind=Letter¦PrintScaleMode=1
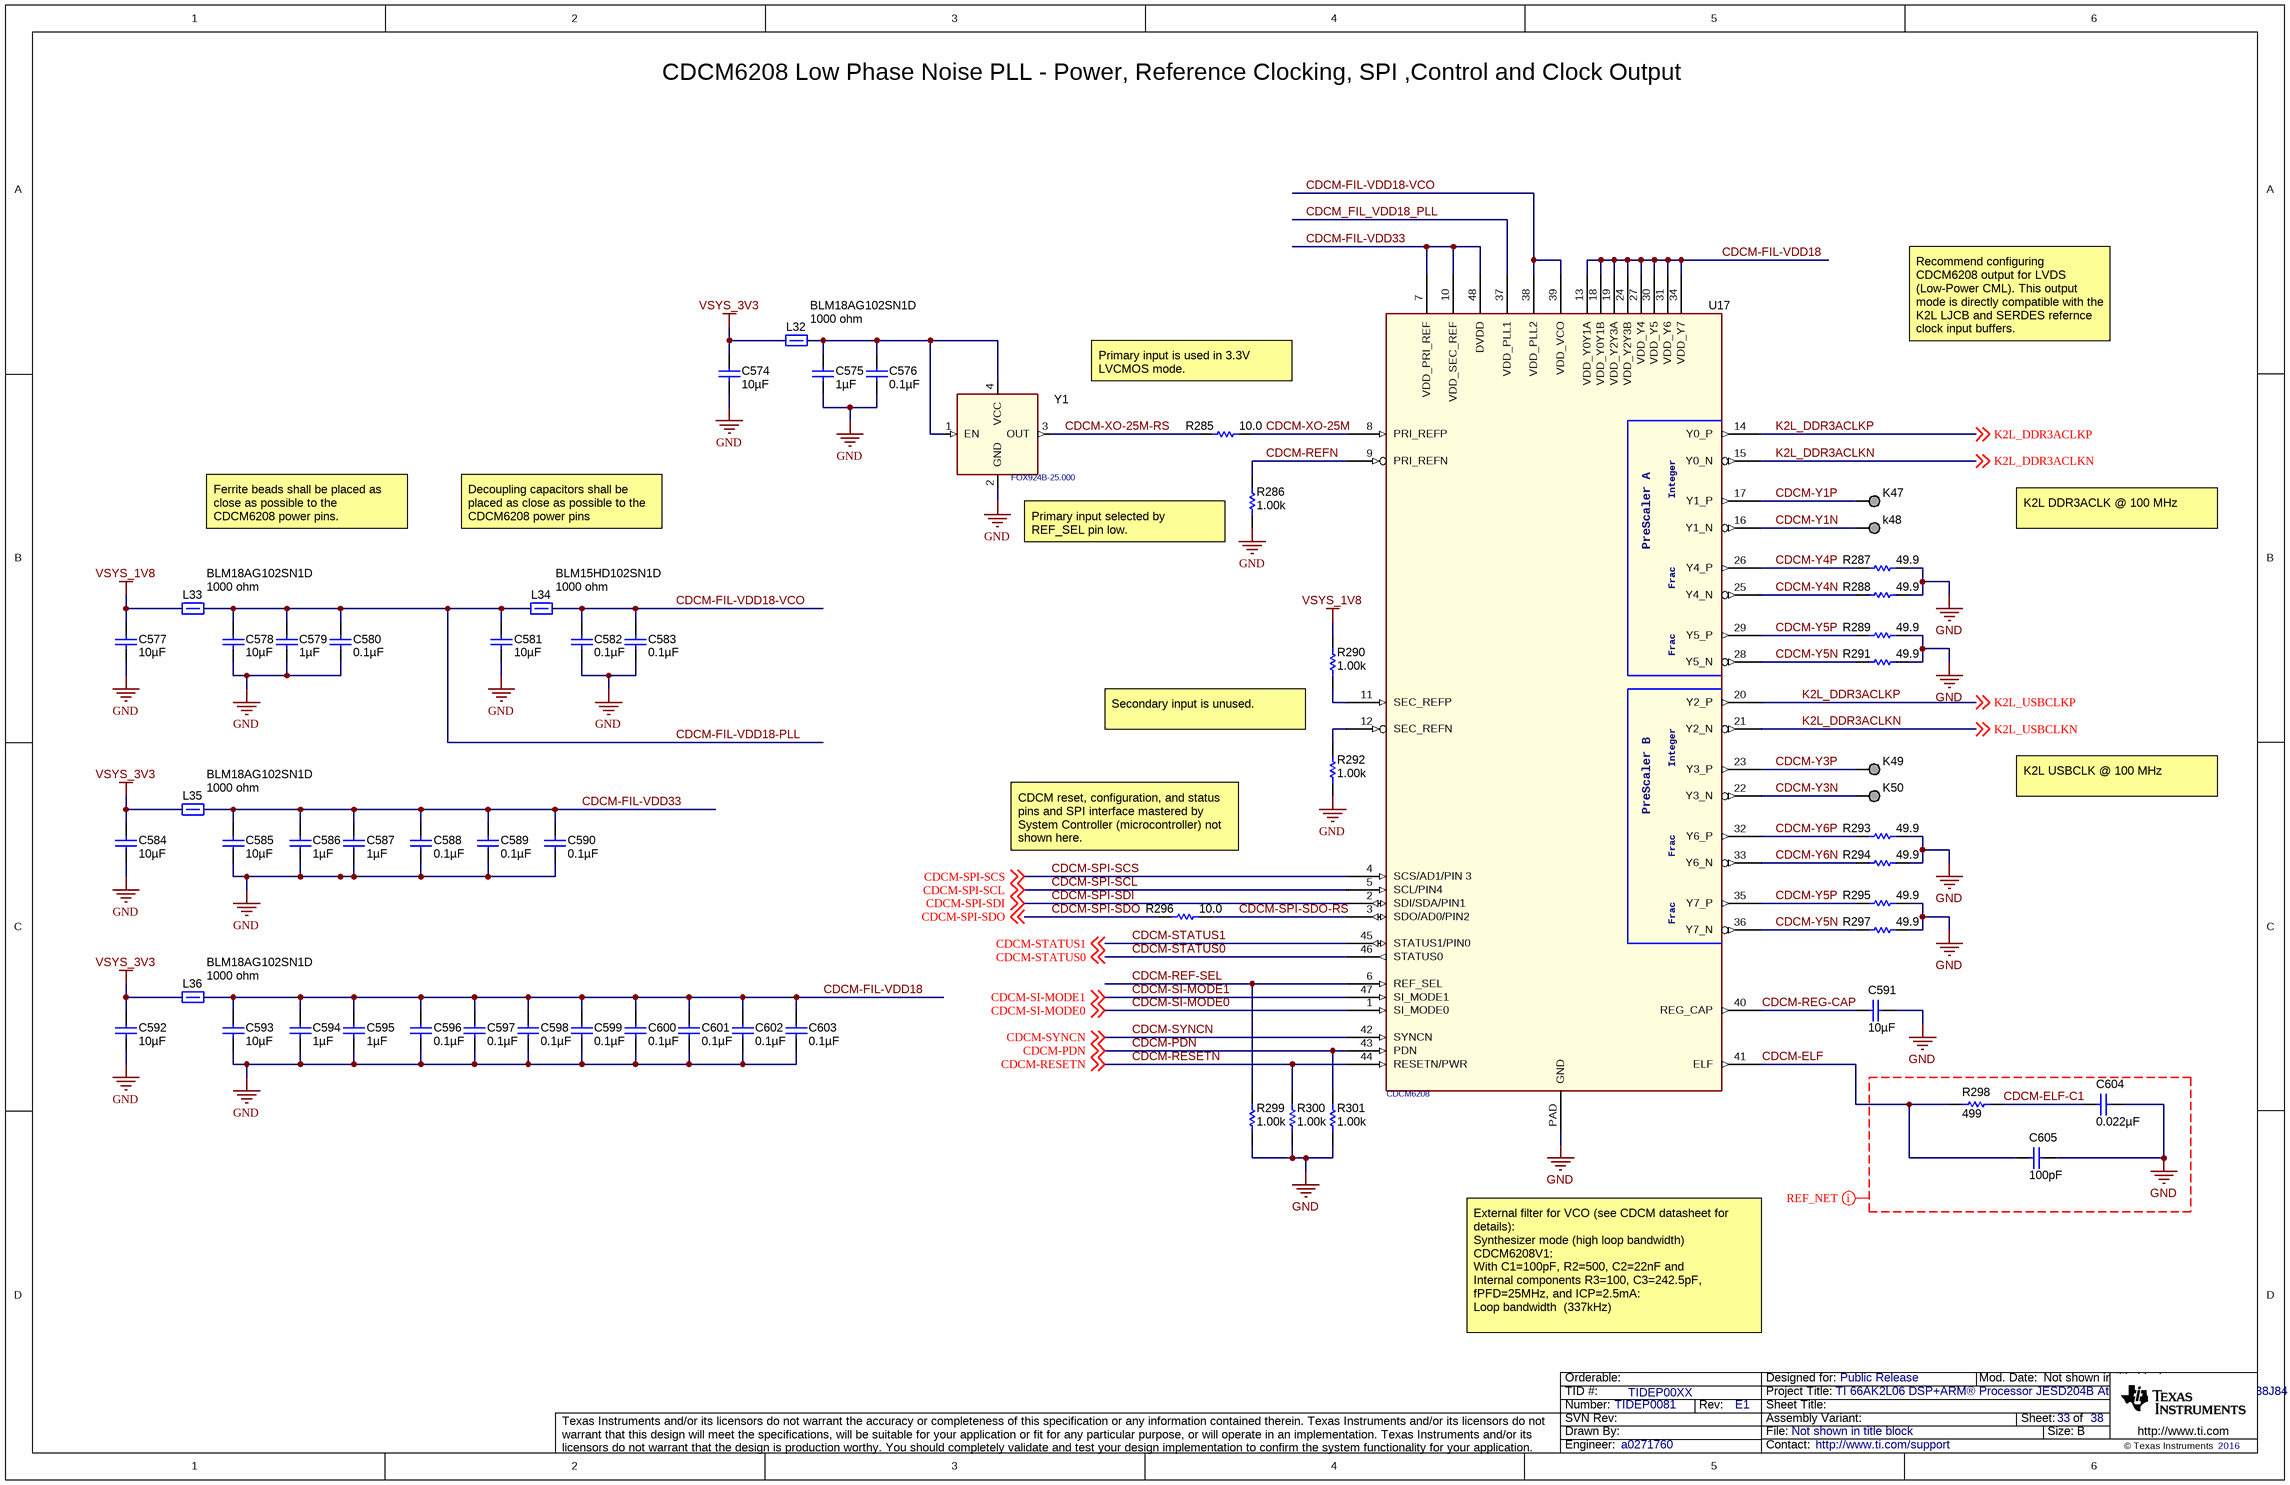
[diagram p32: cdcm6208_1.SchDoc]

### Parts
C574  ValueDisplayed: 10µF  [0805_HV]  (hidden comment: GRM21BF50J106ZE01L)
C575  ValueDisplayed: 1µF  [0603]  (hidden comment: GRM188R70J105KA01D)
C576  ValueDisplayed: 0.1µF  [0603]  (hidden comment: GRM188R70J104KA01D)
C577  ValueDisplayed: 10µF  [0805_HV]  (hidden comment: GRM21BF50J106ZE01L)
C578  ValueDisplayed: 10µF  [0805_HV]  (hidden comment: GRM21BF50J106ZE01L)
C579  ValueDisplayed: 1µF  [0603]  (hidden comment: GRM188R70J105KA01D)
C580  ValueDisplayed: 0.1µF  [0603]  (hidden comment: GRM188R70J104KA01D)
C581  ValueDisplayed: 10µF  [0805_HV]  (hidden comment: GRM21BF50J106ZE01L)
C582  ValueDisplayed: 0.1µF  [0603]  (hidden comment: GRM188R70J104KA01D)
C583  ValueDisplayed: 0.1µF  [0603]  (hidden comment: GRM188R70J104KA01D)
C584  ValueDisplayed: 10µF  [0805_HV]  (hidden comment: GRM21BF50J106ZE01L)
C585  ValueDisplayed: 10µF  [0805_HV]  (hidden comment: GRM21BF50J106ZE01L)
C586  ValueDisplayed: 1µF  [0603]  (hidden comment: GRM188R70J105KA01D)
C587  ValueDisplayed: 1µF  [0603]  (hidden comment: GRM188R70J105KA01D)
C588  ValueDisplayed: 0.1µF  [0603]  (hidden comment: GRM188R70J104KA01D)
C589  ValueDisplayed: 0.1µF  [0603]  (hidden comment: GRM188R70J104KA01D)
C590  ValueDisplayed: 0.1µF  [0603]  (hidden comment: GRM188R70J104KA01D)
C591  ValueDisplayed: 10µF  [0805_HV]  (hidden comment: GRM21BF50J106ZE01L)
C592  ValueDisplayed: 10µF  [0805_HV]  (hidden comment: GRM21BF50J106ZE01L)
C593  ValueDisplayed: 10µF  [0805_HV]  (hidden comment: GRM21BF50J106ZE01L)
C594  ValueDisplayed: 1µF  [0603]  (hidden comment: GRM188R70J105KA01D)
C595  ValueDisplayed: 1µF  [0603]  (hidden comment: GRM188R70J105KA01D)
C596  ValueDisplayed: 0.1µF  [0603]  (hidden comment: GRM188R70J104KA01D)
C597  ValueDisplayed: 0.1µF  [0603]  (hidden comment: GRM188R70J104KA01D)
C598  ValueDisplayed: 0.1µF  [0603]  (hidden comment: GRM188R70J104KA01D)
C599  ValueDisplayed: 0.1µF  [0603]  (hidden comment: GRM188R70J104KA01D)
C600  ValueDisplayed: 0.1µF  [0603]  (hidden comment: GRM188R70J104KA01D)
C601  ValueDisplayed: 0.1µF  [0603]  (hidden comment: GRM188R70J104KA01D)
C602  ValueDisplayed: 0.1µF  [0603]  (hidden comment: GRM188R70J104KA01D)
C603  ValueDisplayed: 0.1µF  [0603]  (hidden comment: GRM188R70J104KA01D)
C604  ValueDisplayed: 0.022µF  [0402]  (hidden comment: GRM155R71H223KA12D)
C605  ValueDisplayed: 100pF  [0402]  (hidden comment: GRM1555C1H101JA01D)
K47  TESTPOINT  [TESTPOINT]  (value not drawn)  (no BOM)
k48  TESTPOINT  [TESTPOINT]  (value not drawn)  (no BOM)
K49  TESTPOINT  [TESTPOINT]  (value not drawn)  (no BOM)
K50  TESTPOINT  [TESTPOINT]  (value not drawn)  (no BOM)
L32  BLM18AG102SN1D  value 1000 ohm  [0603]
L33  BLM18AG102SN1D  value 1000 ohm  [0603]
L34  BLM15HD102SN1D  value 1000 ohm  [0402]
L35  BLM18AG102SN1D  value 1000 ohm  [0603]
L36  BLM18AG102SN1D  value 1000 ohm  [0603]
R285  ValueDisplayed: 10.0  [0402]  (hidden comment: CRCW040210R0FKED)
R286  ValueDisplayed: 1.00k  [0402]  (hidden comment: CRCW04021K00FKED)
R287  ValueDisplayed: 49.9  [0402]  (hidden comment: CRCW040249R9FKED)
R288  ValueDisplayed: 49.9  [0402]  (hidden comment: CRCW040249R9FKED)
R289  ValueDisplayed: 49.9  [0402]  (hidden comment: CRCW040249R9FKED)
R290  ValueDisplayed: 1.00k  [0402]  (hidden comment: CRCW04021K00FKED)
R291  ValueDisplayed: 49.9  [0402]  (hidden comment: CRCW040249R9FKED)
R292  ValueDisplayed: 1.00k  [0402]  (hidden comment: CRCW04021K00FKED)
R293  ValueDisplayed: 49.9  [0402]  (hidden comment: CRCW040249R9FKED)
R294  ValueDisplayed: 49.9  [0402]  (hidden comment: CRCW040249R9FKED)
R295  ValueDisplayed: 49.9  [0402]  (hidden comment: CRCW040249R9FKED)
R296  ValueDisplayed: 10.0  [0402]  (hidden comment: CRCW040210R0FKED)
R297  ValueDisplayed: 49.9  [0402]  (hidden comment: CRCW040249R9FKED)
R298  ValueDisplayed: 499  [0402]  (hidden comment: CRCW0402499RFKED)
R299  ValueDisplayed: 1.00k  [0402]  (hidden comment: CRCW04021K00FKED)
R300  ValueDisplayed: 1.00k  [0402]  (hidden comment: CRCW04021K00FKED)
R301  ValueDisplayed: 1.00k  [0402]  (hidden comment: CRCW04021K00FKED)
U17  CDCM6208
Y1  FOX924B-25.000

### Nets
GND: C574.2 C575.2 C576.2 C577.2 C578.2 C579.2 C580.2 C581.2 C582.2 C583.2 C584.2 C585.2 C586.2 C587.2 C588.2 C589.2 C590.2 C591.2 C592.2 C593.2 C594.2 C595.2 C596.2 C597.2 C598.2 C599.2 C600.2 C601.2 C602.2 C603.2 C604.1 C605.1 R286.1 R287.1 R288.1 R289.1 R291.1 R292.1 R293.1 R294.1 R295.1 R297.1 R299.1 R300.1 R301.1 U17.PAD(GND) Y1.2(GND)  [project net DAC_OUT0N_T1]
VSYS_1V8: C577.1 L33.1 R290.2
VSYS_3V3: C574.1 C584.1 C592.1 L32.1 L35.1 L36.1
CDCM-ELF: C605.2 R298.1 U17.41(ELF)
CDCM-ELF-C1: C604.2 R298.2
CDCM-FIL-VDD18: C593.1 C594.1 C595.1 C596.1 C597.1 C598.1 C599.1 C600.1 C601.1 C602.1 C603.1 L36.2 U17.13(VDD_Y0Y1A) U17.18(VDD_Y0Y1B) U17.19(VDD_Y2Y3A) U17.24(VDD_Y2Y3B) U17.27(VDD_Y4) U17.30(VDD_Y5) U17.31(VDD_Y6) U17.34(VDD_Y7)
CDCM-FIL-VDD18-PLL: C578.1 C579.1 C580.1 C581.1 L33.2 L34.1
CDCM-FIL-VDD18-VCO: C582.1 C583.1 L34.2 U17.38(VDD_PLL2) U17.39(VDD_VCO)
CDCM-FIL-VDD33: C585.1 C586.1 C587.1 C588.1 C589.1 C590.1 L35.2 U17.7(VDD_PRI_REF) U17.10(VDD_SEC_REF) U17.48(DVDD)
CDCM-PDN: R301.2 U17.43(PDN) ; off-sheet CDCM-PDN
CDCM-REF-SEL: R299.2 U17.6(REF_SEL)
CDCM-REFN: R286.2 U17.9(PRI_REFN)
CDCM-REG-CAP: C591.1 U17.40(REG_CAP)
CDCM-RESETN: R300.2 U17.44(RESETN/PWR) ; off-sheet CDCM-RESETN
CDCM-SI-MODE0: U17.1(SI_MODE0) ; off-sheet CDCM-SI-MODE0
CDCM-SI-MODE1: U17.47(SI_MODE1) ; off-sheet CDCM-SI-MODE1
CDCM-SPI-SCL: U17.5(SCL/PIN4) ; off-sheet CDCM-SPI-SCL
CDCM-SPI-SCS: U17.4(SCS/AD1/PIN_3) ; off-sheet CDCM-SPI-SCS
CDCM-SPI-SDI: U17.2(SDI/SDA/PIN1) ; off-sheet CDCM-SPI-SDI
CDCM-SPI-SDO: R296.1 ; off-sheet CDCM-SPI-SDO
CDCM-SPI-SDO-RS: R296.2 U17.3(SDO/AD0/PIN2)
CDCM-STATUS0: U17.46(STATUS0) ; off-sheet CDCM-STATUS0
CDCM-STATUS1: U17.45(STATUS1/PIN0) ; off-sheet CDCM-STATUS1
CDCM-SYNCN: U17.42(SYNCN) ; off-sheet CDCM-SYNCN
CDCM-XO-25M: R285.2 U17.8(PRI_REFP)
CDCM-XO-25M-RS: R285.1 Y1.3(OUT)
CDCM-Y1N: k48.1 U17.16(Y1_N)
CDCM-Y1P: K47.1 U17.17(Y1_P)
CDCM-Y3N: K50.1 U17.22(Y3_N)
CDCM-Y3P: K49.1 U17.23(Y3_P)
CDCM-Y4N: R288.2 U17.25(Y4_N)
CDCM-Y4P: R287.2 U17.26(Y4_P)
CDCM-Y5N: R291.2 R297.2 U17.28(Y5_N) U17.36(Y7_N)
CDCM-Y5P: R289.2 R295.2 U17.29(Y5_P) U17.35(Y7_P)
CDCM-Y6N: R294.2 U17.33(Y6_N)
CDCM-Y6P: R293.2 U17.32(Y6_P)
CDCM_FIL_VDD18_PLL: U17.37(VDD_PLL1)
K2L_DDR3ACLKN: U17.15(Y0_N) U17.21(Y2_N) ; off-sheet K2L_DDR3ACLKN, off-sheet K2L_USBCLKN  [also labelled K2L_USBCLKN]
K2L_DDR3ACLKP: U17.14(Y0_P) U17.20(Y2_P) ; off-sheet K2L_DDR3ACLKP, off-sheet K2L_USBCLKP  [also labelled K2L_USBCLKP]
NetC575_1: C575.1 C576.1 L32.2 Y1.1(EN) Y1.4(VCC)
NetR290_1: R290.1 U17.11(SEC_REFP)
NetR292_2: R292.2 U17.12(SEC_REFN)

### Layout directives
net class Undefined: CDCM-ELF-C1, GND

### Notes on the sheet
- CDCM6208 Low Phase Noise PLL - Power, Reference Clocking, SPI ,Control and Clock Output
- Recommend configuring CDCM6208 output for LVDS (Low-Power CML). This output mode is directly compatible with the K2L LJCB and SERDES refernce clock input buffers.
- Primary input is used in 3.3V LVCMOS mode.
- Ferrite beads shall be placed as close as possible to the CDCM6208 power pins.
- Decoupling capacitors shall be placed as close as possible to the CDCM6208 power pins
- Primary input selected by REF_SEL pin low.
- K2L DDR3ACLK @ 100 MHz
- Secondary input is unused.
- K2L USBCLK @ 100 MHz
- CDCM reset, configuration, and status pins and SPI interface mastered by System Controller (microcontroller) not shown here.
- External filter for VCO (see CDCM datasheet for details):
  Synthesizer mode (high loop bandwidth)
  CDCM6208V1:
  With C1=100pF, R2=500, C2=22nF and
  Internal components R3=100, C3=242.5pF,
  fPFD=25MHz, and ICP=2.5mA:
  Loop bandwidth  (337kHz)

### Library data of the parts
C574 C577 C578 C581 C584 C585 C591-C593 = GRM21BF50J106ZE01L: CAP, CERM, 10 µF, 6.3 V, +80/-20%, Y5V, 0805; Manufacturer: MuRata; Polarized: N; CompType: Capacitor; Value: 10uF; U/M: EA; Cap_F: 0.00001; Tolerance_%: 80; ESR_ohm: 0.1; Value1: 0.1 ohm; VDC_V: 6.3; Value2: 6.3V; TaMin_C: -30; TaMax_C: 85; Cap_Case: 0805; SizeArea_mm2: 2.5; SizeAreaWB_mm2: 6.75; SizeX_mm: 2; SizeY_mm: 1.25; SizeZ_mm: 1.45; AEC Category: Q200
C575 C579 C586 C587 C594 C595 = GRM188R70J105KA01D: CAP, CERM, 1 µF, 6.3 V, +/- 10%, X7R, 0603; Manufacturer: MuRata; Polarized: N; CompType: Capacitor; Value: 1uF; U/M: EA; Cap_F: 0.000001; Tolerance_%: 10; Value1: Unknown; VDC_V: 6.3; Value2: 6.3V; TaMin_C: -55; TaMax_C: 125; SizeArea_mm2: 1.28; SizeAreaWB_mm2: 4.68; SizeX_mm: 1.6; SizeY_mm: 0.8; SizeZ_mm: 1; AEC Category: Q200
C576 C580 C582 C583 C588-C590 C596-C603 = GRM188R70J104KA01D: CAP, CERM, 0.1 µF, 6.3 V, +/- 10%, X7R, 0603; Manufacturer: MuRata; Polarized: N; CompType: Capacitor; Value: 0.1uF; U/M: EA; Cap_F: 0.0000001; Tolerance_%: 10; Value1: Unknown; VDC_V: 6.3; Value2: 6.3V; TaMin_C: -55; TaMax_C: 125; SizeArea_mm2: 1.28; SizeAreaWB_mm2: 4.68; SizeX_mm: 1.6; SizeY_mm: 0.8; SizeZ_mm: 1; AEC Category: Q200
C604 = GRM155R71H223KA12D: CAP, CERM, 0.022 µF, 50 V, +/- 10%, X7R, 0402; Manufacturer: MuRata; Polarized: N; CompType: Capacitor; Value: 0.022uF; U/M: EA; Cap_F: 0.000000022; Tolerance_%: 10; Value1: Unknown; VDC_V: 50; Value2: 50V; TaMin_C: -55; TaMax_C: 125; SizeArea_mm2: 0.5; SizeAreaWB_mm2: 3; SizeX_mm: 1; SizeZ_mm: 0.6; AEC Category: Q200
C605 = GRM1555C1H101JA01D: CAP, CERM, 100 pF, 50 V, +/- 5%, C0G/NP0, 0402; Manufacturer: MuRata; Polarized: N; CompType: Capacitor; Value: 100pF; U/M: EA; Cap_F: 0.0000000001; Tolerance_%: 5; Value1: Unknown; VDC_V: 50; Value2: 50V; TaMin_C: -55; TaMax_C: 125; SizeArea_mm2: 0.5; SizeAreaWB_mm2: 3; SizeX_mm: 1; SizeZ_mm: 0.6; AEC Category: Q200
K47 k48 K49 K50 = TESTPOINT: TEST POINT.  No entry in BOM.
L32 L33 L35 L36 = BLM18AG102SN1D: Ferrite Bead, 1000 ohm @ 100 MHz, 0.4 A, 0603; Manufacturer: MuRata; Imax_A: 0.4; DCR_ohm: 0.5; Value1: 0.5 ohm; Value2: 0.4A; ZTyp@100MHz_Ohm: 1000
L34 = BLM15HD102SN1D: Ferrite Bead, 1000 ohm @ 100 MHz, 0.25 A, 0402; Manufacturer: MuRata; Imax_A: 0.25; DCR_ohm: 1.25; Value1: 1.25 ohm; Value2: 0.25A; ZTyp@100MHz_Ohm: 1000
R285 R296 = CRCW040210R0FKED: as R277 on sheet lmk04828_02
R286 R290 R292 R299-R301 = CRCW04021K00FKED: RES, 1.00 k, 1%, 0.063 W, 0402; Manufacturer: Vishay-Dale; CompType: Resistor; Value: 1.00k; Res_ohm: 1000; Value_Code: 1k00; Tolerance_%: 1; Power_W: 0.063; Value2: 0.063W; VDC_V: 50; TempCo: 100 ppm/C; EIA_Code: E96; U/M: EA
R287-R289 R291 R293-R295 R297 = CRCW040249R9FKED: as R210 on sheet dac38j84_03
R298 = CRCW0402499RFKED: RES, 499, 1%, 0.063 W, 0402; Manufacturer: Vishay-Dale; CompType: Resistor; Value: 499; Value_Code: 499R; Tolerance_%: 1; Power_W: 0.063; Value2: 0.063W; VDC_V: 50; TempCo: 100 ppm/C; SizeArea_mm2: 0.5; SizeZ_mm: 0.6; EIA_Code: E96; U/M: EA; AEC Category: Q200
Y1 = XO-4P: Manufacturer: Fox Electronics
